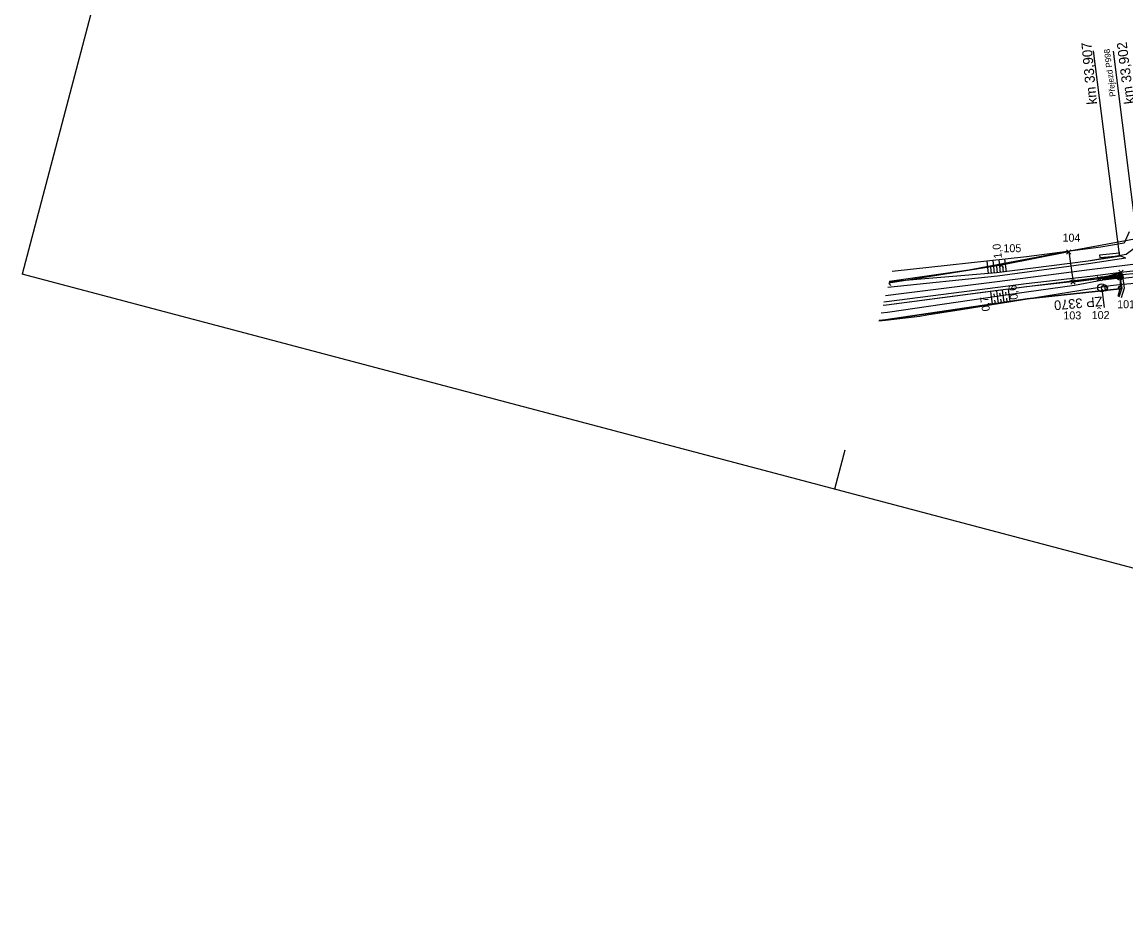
# Model space of a CAD drawing. Extents: x -805011 to -803920, y -1150790 to -1150234.
# Drawn here: x -805011.3 to -804735.5, y -1150682.7 to -1150458.6 of the extents above; entities that cross this region are included whole.
import ezdxf

# ---------------------------------------------------------------- set-up
doc = ezdxf.new("R2010")
doc.units = 0
for name, color, linetype in [('0381KM032-037P - Vrstva 1', 7, 'Continuous'), ('0381KM032-037P - Vrstva 13', 7, 'Continuous'), ('0381KM032-037P - Vrstva 17', 7, 'Continuous'), ('0381KM032-037P - Vrstva 25', 7, 'Continuous'), ('0381KM032-037P - Vrstva 36', 7, 'Continuous'), ('0381KM032-037P - Vrstva 4', 7, 'Continuous'), ('0381KM032-037P - Vrstva 43', 7, 'Continuous'), ('0381KM032-037P - Vrstva 48', 7, 'Continuous'), ('0381KM032-037P - Vrstva 49', 7, 'Continuous'), ('0381KM032-037P - Vrstva 51', 7, 'Continuous'), ('0381KM032-037P - Vrstva 9', 7, 'Continuous'), ('Default', 7, 'Continuous'), ('formát', 7, 'Continuous'), ('hran DP - hran DP', 7, 'Continuous'), ('PSR_C2_2_Lomove_body_Vimperk - Vrstva 60', 7, 'Continuous'), ('PSR_C2_2_trasa_Vimperk - Kabelová trasa', 7, 'Continuous'), ('vyt_sit - stávající', 7, 'Continuous')]:
    doc.layers.add(name, color=color, linetype=linetype)

msp = doc.modelspace()

# ---------------------------------------------------------------- linework, layer by layer
at = {"layer": '0381KM032-037P - Vrstva 1'}
for points in [[(-804485.9, -1150487.74), (-804508.11, -1150490.55), (-804529.67, -1150493.3), (-804537.63, -1150494.31), (-804546.61, -1150495.46), (-804554.2, -1150496.42), (-804564.05, -1150497.67), (-804586.01, -1150500.48), (-804607.92, -1150503.26), (-804630.35, -1150506.11), (-804652.65, -1150508.9), (-804675.7, -1150511.78), (-804698.85, -1150514.71), (-804701.61, -1150515.06), (-804722.18, -1150517.67), (-804729.05, -1150518.54), (-804735.1, -1150519.31), (-804744.56, -1150520.5), (-804767.65, -1150523.46), (-804791, -1150526.42)], [(-804791, -1150526.42), (-804795.53, -1150527)]]:
    msp.add_lwpolyline(points, dxfattribs=at)
at = {"layer": '0381KM032-037P - Vrstva 13'}
msp.add_line((-804736.93, -1150522.56), (-804736.22, -1150522.62), dxfattribs=at)
for points in [[(-804736.32, -1150521.88), (-804741.33, -1150522.48), (-804741.32, -1150522.62), (-804736.39, -1150522.04)], [(-804736.33, -1150522.27), (-804741.29, -1150522.87), (-804741.32, -1150522.62)], [(-804741.29, -1150522.87), (-804741.28, -1150522.98), (-804736.24, -1150522.43)], [(-804736.93, -1150522.56), (-804736.54, -1150525.1), (-804737.22, -1150527.34)], [(-804736.22, -1150522.62), (-804735.92, -1150525.05), (-804736.64, -1150527.49)], [(-804736.32, -1150521.88), (-804736.39, -1150522.04), (-804736.33, -1150522.27), (-804736.24, -1150522.43)]]:
    msp.add_lwpolyline(points, dxfattribs=at)
at = {"layer": '0381KM032-037P - Vrstva 17'}
for points in [[(-804734.71, -1150510.96), (-804735.96, -1150513.84), (-804741.77, -1150514.83), (-804760.36, -1150517.2), (-804793.92, -1150520.9)], [(-804797.16, -1150533.15), (-804795.6, -1150532.98), (-804760.14, -1150527.72), (-804737.02, -1150525.24), (-804737.52, -1150527.15)]]:
    msp.add_lwpolyline(points, dxfattribs=at)
at = {"layer": '0381KM032-037P - Vrstva 25'}
for p, q in [((-804737.43, -1150521.73), (-804736.43, -1150522.84)), ((-804737.41, -1150522.86), (-804736.43, -1150521.74)), ((-804736.93, -1150523.04), (-804736.93, -1150524.54)), ((-804737.32, -1150525.02), (-804736.85, -1150524.55)), ((-804737.06, -1150525.32), (-804736.56, -1150524.82))]:
    msp.add_line(p, q, dxfattribs=at)
for centre, radius in [((-804736.94, -1150522.29), 0.749), ((-804736.93, -1150524.94), 0.4), ((-804736.93, -1150524.94), 0.4)]:
    msp.add_circle(centre, radius, dxfattribs=at)
at = {"layer": '0381KM032-037P - Vrstva 36'}
for p, q in [((-804741.54, -1150524.95), (-804741.54, -1150524.95)), ((-804741.41, -1150525.95), (-804740.91, -1150529.91))]:
    msp.add_line(p, q, dxfattribs=at)
msp.add_circle((-804741.54, -1150524.95), 1, dxfattribs=at)
at = {"layer": '0381KM032-037P - Vrstva 4'}
msp.add_line((-804738.68, -1150465.82), (-804731.99, -1150518.9), dxfattribs=at)
for points in [[(-804735.49, -1150517.59), (-804736.73, -1150517.05), (-804744.9, -1150518.34), (-804767.83, -1150521.26)], [(-804735.49, -1150517.59), (-804744.82, -1150519), (-804767.55, -1150522.1)], [(-804767.55, -1150522.1), (-804794.99, -1150524.93)], [(-804767.83, -1150521.26), (-804794.61, -1150523.51)], [(-804736.74, -1150521.15), (-804737.38, -1150521.73), (-804744.34, -1150522.73), (-804767.48, -1150525.67)], [(-804736.74, -1150521.15), (-804744.39, -1150522.13), (-804760.4, -1150524), (-804767.46, -1150524.91)], [(-804767.48, -1150525.67), (-804795.35, -1150529.3), (-804796.17, -1150529.4)], [(-804767.46, -1150524.91), (-804795.31, -1150528.51), (-804795.96, -1150528.6)]]:
    msp.add_lwpolyline(points, dxfattribs=at)
at = {"layer": '0381KM032-037P - Vrstva 43'}
msp.add_lwpolyline([(-804736.33, -1150521.65), (-804729.5, -1150520.98), (-804729.45, -1150521.92), (-804736.22, -1150522.62)], close=True, dxfattribs=at)
at = {"layer": '0381KM032-037P - Vrstva 48'}
for p, q in [((-804769.83, -1150521.43), (-804770.13, -1150518.28)), ((-804769.08, -1150521.37), (-804769.23, -1150519.78)), ((-804768.33, -1150521.3), (-804768.64, -1150518.12)), ((-804767.55, -1150521.23), (-804767.74, -1150519.63)), ((-804766.81, -1150521.13), (-804767.19, -1150517.96)), ((-804766.07, -1150521.04), (-804766.25, -1150519.46)), ((-804765.32, -1150520.94), (-804765.7, -1150517.79)), ((-804769.09, -1150527.24), (-804769.27, -1150525.92)), ((-804767.6, -1150527.03), (-804767.78, -1150525.73)), ((-804766.12, -1150526.81), (-804766.3, -1150525.53)), ((-804764.64, -1150526.59), (-804764.81, -1150525.34)), ((-804768.83, -1150529.01), (-804769.09, -1150527.24)), ((-804768.35, -1150527.13), (-804768.44, -1150526.48)), ((-804768.09, -1150528.9), (-804768.22, -1150528.02)), ((-804767.35, -1150528.79), (-804767.61, -1150527.03)), ((-804766.86, -1150526.92), (-804766.95, -1150526.27)), ((-804766.61, -1150528.68), (-804766.74, -1150527.8)), ((-804765.87, -1150528.57), (-804766.12, -1150526.81)), ((-804765.38, -1150526.7), (-804765.46, -1150526.07)), ((-804765.12, -1150528.46), (-804765.25, -1150527.58)), ((-804764.38, -1150528.35), (-804764.64, -1150526.59))]:
    msp.add_line(p, q, dxfattribs=at)
at = {"layer": '0381KM032-037P - Vrstva 49'}
for points in [[(-804731.33, -1150510.42), (-804733.06, -1150514.89), (-804735.43, -1150516.61), (-804744.9, -1150518.34), (-804767.83, -1150521.26), (-804794.61, -1150523.51)], [(-804735.96, -1150513.84), (-804741.77, -1150514.83), (-804760.36, -1150517.2), (-804793.92, -1150520.9)], [(-804796.66, -1150531.24), (-804795.08, -1150531.02), (-804760.31, -1150525.97), (-804748.35, -1150524.3), (-804741.28, -1150522.98)], [(-804741.32, -1150522.62), (-804760.31, -1150524.76), (-804795.35, -1150529.3), (-804796.17, -1150529.4)], [(-804741.32, -1150522.62), (-804741.29, -1150522.87), (-804741.28, -1150522.98)], [(-804737.02, -1150525.24), (-804760.14, -1150527.72), (-804795.6, -1150532.98), (-804797.16, -1150533.15)]]:
    msp.add_lwpolyline(points, dxfattribs=at)
at = {"layer": '0381KM032-037P - Vrstva 51'}
msp.add_lwpolyline([(-804736.22, -1150522.62), (-804735.92, -1150525.05), (-804736.64, -1150527.49)], dxfattribs=at)
at = {"layer": '0381KM032-037P - Vrstva 9'}
for p, q in [((-804737.08, -1150516.65), (-804743.56, -1150465.71)), ((-804737.11, -1150516.35), (-804742.09, -1150516.81)), ((-804742.09, -1150516.81), (-804742.04, -1150517.41)), ((-804742.04, -1150517.41), (-804737.06, -1150516.95)), ((-804737.11, -1150516.35), (-804737.17, -1150515.76)), ((-804737.06, -1150516.95), (-804737.11, -1150516.35))]:
    msp.add_line(p, q, dxfattribs=at)
at = {"layer": 'formát'}
for p, q in [((-804935.34, -1150234.42), (-805011.32, -1150521.54)), ((-804402.28, -1150682.7), (-805011.32, -1150521.54)), ((-804805.75, -1150565.59), (-804808.3, -1150575.26))]:
    msp.add_line(p, q, dxfattribs=at)
at = {"layer": 'hran DP - hran DP'}
for p, q in [((-804747.72, -1150515.43), (-804723.03, -1150510.78)), ((-804774.72, -1150520.52), (-804747.72, -1150515.43)), ((-804794.57, -1150523.35), (-804774.72, -1150520.52)), ((-804744.2, -1150525.25), (-804766.8, -1150528.89)), ((-804739.31, -1150524.46), (-804744.2, -1150525.25)), ((-804736.36, -1150524.18), (-804739.31, -1150524.46)), ((-804729.97, -1150523.63), (-804736.36, -1150524.18)), ((-804776.65, -1150530.47), (-804785.22, -1150531.85)), ((-804766.8, -1150528.89), (-804776.65, -1150530.47)), ((-804795.52, -1150533.13), (-804797.21, -1150533.33)), ((-804786.96, -1150532.13), (-804795.52, -1150533.13)), ((-804785.22, -1150531.85), (-804786.96, -1150532.13))]:
    msp.add_line(p, q, dxfattribs=at)
at = {"layer": 'PSR_C2_2_Lomove_body_Vimperk - Vrstva 60'}
for p, q in [((-804750.33, -1150516.54), (-804749.23, -1150515.44)), ((-804749.23, -1150516.54), (-804750.33, -1150515.44)), ((-804767.15, -1150519.9), (-804766.05, -1150518.8)), ((-804766.05, -1150519.9), (-804767.15, -1150518.8)), ((-804749.23, -1150524.1), (-804748.13, -1150523)), ((-804748.13, -1150524.1), (-804749.23, -1150523)), ((-804742.67, -1150523.27), (-804741.57, -1150522.17)), ((-804741.57, -1150523.27), (-804742.67, -1150522.17)), ((-804737.29, -1150521.7), (-804736.19, -1150520.59)), ((-804736.19, -1150521.7), (-804737.29, -1150520.59)), ((-804794.24, -1150524.41), (-804794.72, -1150523.93)), ((-804794.67, -1150523.74), (-804794.24, -1150523.31))]:
    msp.add_line(p, q, dxfattribs=at)
at = {"layer": 'PSR_C2_2_trasa_Vimperk - Kabelová trasa'}
for p, q in [((-804749.78, -1150515.99), (-804766.6, -1150519.35)), ((-804749.78, -1150515.99), (-804748.68, -1150523.55)), ((-804728.64, -1150520.2), (-804736.74, -1150521.15)), ((-804742.12, -1150522.72), (-804748.68, -1150523.55)), ((-804736.74, -1150521.15), (-804742.12, -1150522.72))]:
    msp.add_line(p, q, dxfattribs=at)
msp.add_lwpolyline([(-804766.6, -1150519.35), (-804794.7, -1150523.84)], dxfattribs=at)
at = {"layer": 'vyt_sit - stávající'}
msp.add_line((-804740.89, -1150524.99), (-804740.79, -1150524.99), dxfattribs=at)
msp.add_circle((-804740.83, -1150524.99), 0.756, dxfattribs=at)

# ---------------------------------------------------------------- texts
at = {"layer": '0381KM032-037P - Vrstva 4'}
for s, height, p in [('km 33,902', 2.5, (-804733.36, -1150478.88)), ('Přejezd P998', 1.5, (-804738.02, -1150477.13))]:
    msp.add_text(s, height=height, rotation=97.1938, dxfattribs=at).set_placement(p)
at = {"layer": '0381KM032-037P - Vrstva 48'}
for s, rotation, p in [('1,0', 96.2855, (-804766.46, -1150517.56)), ('0,6', 97.4164, (-804762.42, -1150527.82)), ('0,7', 98.2601, (-804769.42, -1150530.71))]:
    msp.add_text(s, height=2, rotation=rotation, dxfattribs=at).set_placement(p)
at = {"layer": '0381KM032-037P - Vrstva 9'}
msp.add_text('km 33,907', height=2.5, rotation=95.2837, dxfattribs=at).set_placement((-804742.69, -1150479.05))
at = {"layer": 'Default'}
for s, p in [('104', (-804751.32, -1150513.44)), ('105', (-804766.09, -1150516.07)), ('101', (-804737.67, -1150530.07)), ('103', (-804751.11, -1150532.87)), ('102', (-804744.03, -1150532.78))]:
    msp.add_text(s, height=2, dxfattribs=at).set_placement(p)
at = {"layer": 'vyt_sit - stávající'}
msp.add_text('ŽP 3370', height=2.4, rotation=185, dxfattribs=at).set_placement((-804741.45, -1150527.14))

doc.saveas('drawing.dxf')
